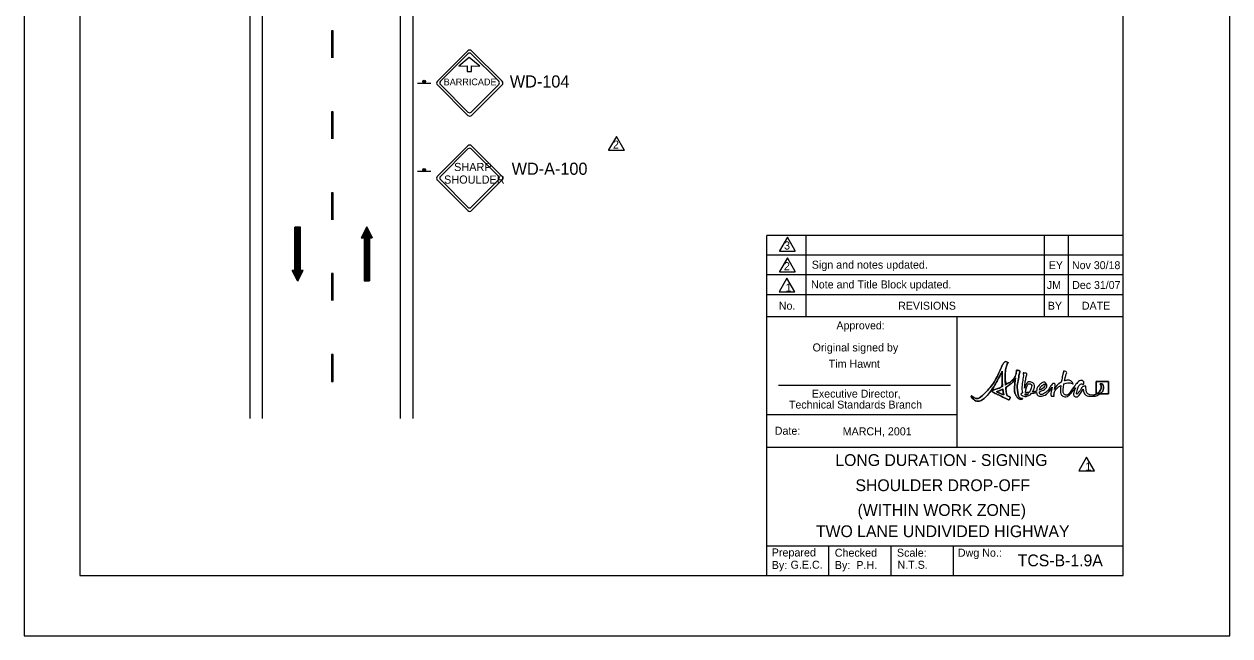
# Model space of a CAD drawing. Extents: x 1387 to 1603, y 134 to 413.
# Drawn here: x 1386.9 to 1602.9, y 133.8 to 243.5 of the extents above; entities that cross this region are included whole.
import ezdxf

# ---------------------------------------------------------------- set-up
doc = ezdxf.new("R2010")
doc.units = 0
for name, color, linetype in [('Level 10', 7, 'Continuous'), ('Level 2', 7, 'Continuous'), ('Level 44', 7, 'Continuous'), ('Level 53', 7, 'Continuous'), ('Level 60', 7, 'Continuous')]:
    doc.layers.add(name, color=color, linetype=linetype)

msp = doc.modelspace()

# ---------------------------------------------------------------- linework, layer by layer
at = {"layer": 'Level 10'}
for p, q in [((1427.31, 354.27), (1427.31, 172.77)), ((1429.55, 354.27), (1429.55, 172.77)), ((1454.23, 354.27), (1454.23, 172.77)), ((1456.49, 269.76), (1456.49, 172.77)), ((1435.4, 199.31), (1435.4, 207.05)), ((1436.37, 207.05), (1435.4, 207.05)), ((1435.4, 198.34), (1435.4, 207.05)), ((1435.52, 198.1), (1435.52, 207.05)), ((1435.64, 197.86), (1435.64, 207.05)), ((1435.76, 197.62), (1435.76, 207.05)), ((1435.88, 197.38), (1435.88, 207.05)), ((1436, 197.62), (1436, 207.05)), ((1436.12, 197.86), (1436.12, 207.05)), ((1436.25, 198.1), (1436.25, 207.05)), ((1436.37, 199.31), (1436.37, 207.05)), ((1436.37, 198.34), (1436.37, 207.05)), ((1448.25, 207.11), (1447.28, 205.17)), ((1447.4, 205.41), (1447.4, 205.17)), ((1447.53, 205.66), (1447.53, 205.17)), ((1447.65, 205.9), (1447.65, 205.17)), ((1447.77, 206.14), (1447.77, 197.43)), ((1447.89, 206.38), (1447.89, 197.43)), ((1448.01, 206.62), (1448.01, 197.43)), ((1448.13, 206.87), (1448.13, 197.43)), ((1448.25, 207.11), (1448.25, 197.43)), ((1448.25, 207.11), (1449.22, 205.17)), ((1448.37, 206.87), (1448.37, 197.43)), ((1448.49, 206.62), (1448.49, 197.43)), ((1448.61, 206.38), (1448.61, 197.43)), ((1448.73, 206.14), (1448.73, 197.43)), ((1448.86, 205.9), (1448.86, 205.17)), ((1448.98, 205.66), (1448.98, 205.17)), ((1449.1, 205.41), (1449.1, 205.17)), ((1447.28, 205.17), (1447.77, 205.17)), ((1447.77, 205.17), (1447.77, 197.43)), ((1448.73, 205.17), (1448.73, 197.43)), ((1448.73, 205.17), (1449.22, 205.17)), ((1435.88, 197.38), (1434.92, 199.31)), ((1435.4, 199.31), (1434.92, 199.31)), ((1435.04, 199.07), (1435.04, 199.31)), ((1435.16, 198.83), (1435.16, 199.31)), ((1435.28, 198.58), (1435.28, 199.31)), ((1435.88, 197.38), (1436.85, 199.31)), ((1436.85, 199.31), (1436.37, 199.31)), ((1436.49, 198.58), (1436.49, 199.31)), ((1436.61, 198.83), (1436.61, 199.31)), ((1436.73, 199.07), (1436.73, 199.31)), ((1447.77, 197.43), (1448.73, 197.43))]:
    msp.add_line(p, q, dxfattribs=at)
at = {"layer": 'Level 2'}
for p, q in [((1441.94, 242.26), (1441.94, 237.42)), ((1442.24, 242.26), (1441.94, 242.26)), ((1442.24, 237.42), (1442.24, 242.26)), ((1441.94, 227.74), (1441.94, 222.91)), ((1442.24, 227.74), (1441.94, 227.74)), ((1442.24, 222.91), (1442.24, 227.74)), ((1441.94, 213.23), (1441.94, 208.39)), ((1442.24, 213.23), (1441.94, 213.23)), ((1442.24, 208.39), (1442.24, 213.23)), ((1441.94, 198.72), (1441.94, 193.88)), ((1442.24, 198.72), (1441.94, 198.72)), ((1442.24, 193.88), (1442.24, 198.72)), ((1441.94, 184.2), (1441.94, 179.36)), ((1442.24, 184.2), (1441.94, 184.2)), ((1442.24, 179.36), (1442.24, 184.2)), ((1441.94, 179.36), (1442.24, 179.36))]:
    msp.add_line(p, q, dxfattribs=at)
at = {"layer": 'Level 44'}
for p, q in [((1466.38, 238.69), (1460.91, 233.22)), ((1461.45, 233.22), (1466.38, 238.14)), ((1466.97, 238.14), (1471.89, 233.22)), ((1472.5, 233.22), (1467.03, 238.69)), ((1466.62, 237.49), (1464.74, 235.91)), ((1464.74, 235.91), (1466.25, 235.99)), ((1466.25, 235.99), (1466.25, 234.99)), ((1468.51, 235.91), (1466.62, 237.49)), ((1467, 234.99), (1467, 235.99)), ((1467, 235.99), (1468.51, 235.91)), ((1466.25, 234.99), (1467, 234.99)), ((1457.34, 232.89), (1459.76, 232.89)), ((1460.91, 232.57), (1466.38, 227.1)), ((1460.91, 232.57), (1460.91, 232.57)), ((1466.38, 227.71), (1461.45, 232.63)), ((1471.89, 232.63), (1466.97, 227.71)), ((1467.03, 227.1), (1472.5, 232.57)), ((1466.39, 221.65), (1460.89, 216.17)), ((1461.44, 216.16), (1466.39, 221.1)), ((1466.97, 221.1), (1471.91, 216.16)), ((1472.52, 216.17), (1467.03, 221.65)), ((1457.34, 217.09), (1459.76, 217.09)), ((1460.89, 215.52), (1466.39, 210.03)), ((1460.9, 215.52), (1460.89, 215.52)), ((1466.39, 210.64), (1461.44, 215.58)), ((1471.91, 215.58), (1466.97, 210.64)), ((1467.03, 210.03), (1472.52, 215.52))]:
    msp.add_line(p, q, dxfattribs=at)
for centre, radius in [((1458.55, 233.16), 0.242), ((1458.55, 233.16), 0.121), ((1458.55, 217.36), 0.242), ((1458.55, 217.36), 0.121)]:
    msp.add_circle(centre, radius, dxfattribs=at)
for centre, radius, start, end in [((1466.71, 238.37), 0.458, 45, 135), ((1466.67, 237.85), 0.412, 45, 135), ((1461.23, 232.9), 0.458, 135, 225), ((1461.75, 232.92), 0.412, 135, 225), ((1471.6, 232.92), 0.412, 315, 45), ((1472.18, 232.9), 0.458, 315, 45), ((1466.67, 228), 0.412, 225, 315), ((1466.71, 227.42), 0.458, 225, 315), ((1466.71, 221.33), 0.459, 45, 135), ((1466.68, 220.81), 0.413, 45, 135), ((1461.22, 215.84), 0.459, 135, 225), ((1461.74, 215.87), 0.413, 135, 225), ((1471.62, 215.87), 0.413, 315, 45), ((1472.2, 215.84), 0.459, 315, 45), ((1466.68, 210.93), 0.413, 225, 315), ((1466.71, 210.35), 0.459, 225, 315)]:
    msp.add_arc(centre, radius, start, end, dxfattribs=at)
at = {"layer": 'Level 53'}
msp.add_line((1579.55, 177.14), (1579, 177.14), dxfattribs=at)
msp.add_lwpolyline([(1579.55, 177.14), (1581.16, 177.14), (1581.16, 179.37), (1578.93, 179.37), (1578.93, 177.14), (1579, 177.14)], dxfattribs=at)
for points, degree in [([(1565.56, 176.33), (1565.32, 176.37), (1565.01, 176.69), (1564.91, 177.23), (1564.74, 178.2), (1564.84, 179.15), (1565.13, 180.57), (1565.18, 180.84), (1565.36, 181.31), (1564.78, 181.4), (1564.59, 181.42), (1564.69, 181.33), (1564.64, 181.09), (1564.41, 180.03), (1563.55, 179.27), (1562.68, 178.75), (1562.59, 179.97), (1562.63, 181.31), (1562.85, 182.14), (1563.05, 182.83), (1563.28, 182.7), (1562.99, 182.85), (1562.69, 183.01), (1562.37, 182.8), (1562.11, 182.28), (1561.85, 181.77), (1560.66, 178.95), (1558.74, 177.05), (1557.77, 176.08), (1556.88, 176.58), (1556.7, 176.73), (1556.56, 176.85), (1556.51, 176.66), (1556.68, 176.47), (1557.48, 175.61), (1558.63, 176.1), (1559.05, 176.52), (1560.22, 177.69), (1561.57, 180.19), (1562.11, 181.25), (1562.06, 180.65), (1562.05, 179.65), (1562.16, 178.48), (1561.57, 178.19), (1561.04, 178.02), (1560.79, 177.95), (1560.51, 177.88), (1560.35, 177.77), (1560.34, 177.64), (1560.34, 177.51), (1560.52, 177.39), (1560.78, 177.27), (1561.25, 177.04), (1562.62, 176.4), (1562.96, 176.2), (1563.25, 176.03), (1563.39, 176.16), (1563.48, 176.34), (1563.59, 176.58), (1563.28, 176.72), (1562.98, 176.81), (1562.87, 177.2), (1562.78, 177.74), (1562.72, 178.33), (1563.41, 178.76), (1564.1, 179.33), (1564.5, 180.04), (1564.4, 179.45), (1564.14, 177.42), (1564.78, 176.56), (1564.92, 176.37), (1565.24, 176.16), (1565.54, 176.19), (1565.68, 176.21), (1565.76, 176.3), (1565.74, 176.33), (1565.73, 176.36), (1565.64, 176.32), (1565.56, 176.33)], 3), ([(1562.68, 178.75), (1562.59, 179.97), (1562.63, 181.31), (1562.85, 182.14), (1563.05, 182.83), (1563.28, 182.7), (1562.99, 182.85), (1562.69, 183.01), (1562.37, 182.8), (1562.11, 182.28), (1561.85, 181.77), (1560.66, 178.95), (1558.74, 177.05), (1557.77, 176.08), (1556.88, 176.58), (1556.7, 176.73), (1556.56, 176.85), (1556.51, 176.66), (1556.68, 176.47), (1557.48, 175.61), (1558.63, 176.1), (1559.05, 176.52), (1560.22, 177.69), (1561.57, 180.19), (1562.11, 181.25)], 3), ([(1562.11, 181.25), (1562.06, 180.65), (1562.05, 179.65), (1562.16, 178.48)], 2), ([(1565.56, 176.33), (1565.32, 176.37), (1565.01, 176.69), (1564.91, 177.23), (1564.74, 178.2), (1564.84, 179.15), (1565.13, 180.57), (1565.18, 180.84), (1565.36, 181.31), (1564.78, 181.4), (1564.59, 181.42), (1564.69, 181.33), (1564.64, 181.09), (1564.41, 180.03), (1563.55, 179.27), (1562.68, 178.75)], 3), ([(1562.72, 178.33), (1563.41, 178.76), (1564.1, 179.33), (1564.5, 180.04)], 2), ([(1564.5, 180.04), (1564.4, 179.45), (1564.14, 177.42), (1564.78, 176.56), (1564.92, 176.37), (1565.24, 176.16), (1565.54, 176.19), (1565.68, 176.21), (1565.76, 176.3), (1565.74, 176.33), (1565.73, 176.36), (1565.64, 176.32), (1565.56, 176.33)], 3), ([(1566.1, 178.17), (1566.14, 178.74), (1566.23, 179.43), (1566.36, 180.08), (1566.42, 180.35), (1566.6, 180.81), (1566.02, 180.9), (1565.83, 180.93), (1565.86, 180.84), (1565.88, 180.59), (1565.9, 180.26), (1565.52, 178.22), (1565.72, 177.32)], 3), ([(1567.54, 177.51), (1567.95, 178.18), (1567.91, 179.09), (1567.31, 179.25), (1566.6, 179.42), (1566.25, 178.74), (1566.1, 178.17)], 3), ([(1573.25, 179.51), (1573.32, 179.81), (1573.39, 180.11), (1573.47, 180.41), (1573.55, 180.68), (1573.77, 181.14), (1573.19, 181.23), (1573.01, 181.26), (1573.09, 181.17), (1573.03, 180.92), (1572.92, 180.47), (1572.78, 179.87), (1572.67, 179.28)], 3), ([(1578.31, 176.94), (1577.39, 176.94), (1577.15, 177.65), (1577.11, 178.01), (1577.08, 178.24), (1577.13, 178.58), (1576.73, 178.53), (1576.44, 178.5), (1576.19, 177.95), (1575.83, 177.49), (1575.52, 177.09), (1575.38, 177.13), (1575.46, 177.47), (1575.54, 177.9), (1575.9, 178.9), (1576.31, 178.98), (1576.5, 179.01), (1576.57, 178.68), (1576.66, 178.88), (1576.74, 179.09), (1576.66, 179.54), (1576.24, 179.54), (1575.94, 179.54), (1575.59, 179.23), (1575.29, 178.87), (1575.04, 178.56), (1573.76, 176.67), (1573.22, 177.08), (1572.96, 177.27), (1572.99, 178.04), (1573.14, 178.96)], 3), ([(1573.14, 178.96), (1573.78, 179.21), (1574.32, 179.13), (1574.62, 178.98), (1574.76, 178.91), (1574.79, 178.92), (1574.72, 179.08), (1574.63, 179.32), (1574.11, 179.7), (1573.31, 179.53), (1573.29, 179.52), (1573.27, 179.52), (1573.25, 179.51)], 3), ([(1578.93, 179.37), (1578.93, 179.37), (1578.93, 177.14), (1578.93, 177.14), (1578.93, 177.14), (1579, 177.14), (1579, 177.14), (1579.48, 177.43), (1579.81, 177.98), (1579.8, 178.44), (1579.8, 178.83), (1579.6, 178.81), (1579.62, 178.87), (1579.69, 179.03), (1580.18, 178.94), (1580.21, 178.38), (1580.23, 177.91), (1579.99, 177.45), (1579.55, 177.14), (1579.55, 177.14), (1581.16, 177.14), (1581.16, 177.14), (1581.16, 177.14), (1581.16, 179.37), (1581.16, 179.37), (1581.16, 179.37), (1578.93, 179.37), (1578.93, 179.37)], 3), ([(1562.16, 178.48), (1561.57, 178.19), (1561.04, 178.02), (1560.79, 177.95), (1560.51, 177.88), (1560.35, 177.77), (1560.34, 177.64), (1560.34, 177.51), (1560.52, 177.39), (1560.78, 177.27), (1561.25, 177.04), (1562.62, 176.4), (1562.96, 176.2), (1563.25, 176.03), (1563.39, 176.16), (1563.48, 176.34), (1563.59, 176.58), (1563.28, 176.72), (1562.98, 176.81)], 3), ([(1561.09, 177.54), (1561.4, 177.66), (1561.79, 177.82), (1562.2, 178.04)], 2), ([(1561.09, 177.54), (1561.4, 177.66), (1561.79, 177.82), (1562.2, 178.04), (1562.26, 177.56), (1562.32, 177.22), (1562.39, 176.97), (1562.09, 177.08), (1561.65, 177.25), (1561.09, 177.54)], 3), ([(1562.39, 176.97), (1562.09, 177.08), (1561.65, 177.25), (1561.09, 177.54)], 2), ([(1562.2, 178.04), (1562.26, 177.56), (1562.32, 177.22), (1562.39, 176.97)], 2), ([(1562.98, 176.81), (1562.87, 177.2), (1562.78, 177.74), (1562.72, 178.33)], 2), ([(1565.72, 177.32), (1565.47, 177.24), (1565.36, 177.05), (1565.69, 176.85), (1565.91, 176.71), (1566.4, 176.67), (1566.9, 176.91), (1567.07, 177), (1567.23, 177.12), (1567.35, 177.27)], 3), ([(1566.17, 176.95), (1566.2, 176.98), (1566.22, 177.02), (1566.22, 177.07), (1566.22, 177.1), (1566.23, 177.13), (1566.23, 177.16)], 3), ([(1566.23, 177.16), (1566.35, 177.17), (1566.55, 177.18), (1566.78, 177.2)], 2), ([(1566.25, 177.38), (1566.34, 178.1), (1566.71, 179.09), (1567.18, 178.93), (1567.45, 178.84), (1567.31, 178), (1566.96, 177.44)], 3), ([(1566.96, 177.44), (1566.74, 177.42), (1566.5, 177.4), (1566.25, 177.38)], 2), ([(1566.78, 177.2), (1566.66, 177.07), (1566.52, 176.97), (1566.37, 176.95)], 2), ([(1567.35, 177.27), (1567.65, 177.3), (1567.96, 177.35), (1568.24, 177.41)], 2), ([(1568.24, 177.63), (1568.03, 177.59), (1567.8, 177.55), (1567.54, 177.51)], 2), ([(1568.76, 177.53), (1568.86, 177.56), (1568.94, 177.59), (1569.02, 177.63), (1569.9, 178.02), (1570.2, 178.61), (1569.98, 178.97), (1569.77, 179.31), (1569.16, 179.2), (1568.68, 178.7), (1568.44, 178.45), (1568.26, 178.02), (1568.24, 177.63)], 3), ([(1568.24, 177.41), (1568.29, 177.02), (1568.55, 176.71), (1569.14, 176.77), (1569.99, 176.85), (1570.74, 177.89), (1571.02, 178.39)], 3), ([(1571.44, 177.95), (1571.49, 178.22), (1571.58, 178.53), (1571.58, 178.74), (1571.59, 178.95), (1571.44, 179), (1571.38, 179.02), (1571.26, 179.06), (1571.11, 178.99), (1570.95, 178.78), (1570.6, 178.28), (1570.15, 177.5), (1569.47, 177.17), (1568.99, 176.93), (1568.77, 177.17), (1568.76, 177.53)], 3), ([(1569.23, 178.65), (1569.53, 178.93), (1569.68, 178.91), (1569.72, 178.83), (1569.8, 178.67), (1569.45, 178.11), (1568.78, 177.8)], 3), ([(1568.78, 177.8), (1568.84, 178.11), (1569, 178.44), (1569.23, 178.65)], 2), ([(1571.02, 178.39), (1570.97, 177.85), (1570.62, 176.68), (1571.22, 176.74), (1571.45, 176.76), (1571.35, 176.8), (1571.37, 177), (1571.42, 177.71), (1572, 178.31), (1572.59, 178.68)], 3), ([(1572.67, 179.28), (1572.2, 179), (1571.76, 178.55), (1571.44, 177.95)], 2), ([(1572.59, 178.68), (1572.49, 177.81), (1572.52, 177.04), (1572.91, 176.79), (1573.64, 176.34), (1574.66, 177.53), (1575.22, 178.26)], 3), ([(1575.22, 178.26), (1574.93, 177.61), (1574.77, 176.78), (1575.2, 176.66), (1575.71, 176.51), (1576.1, 177.35), (1576.57, 177.99)], 3), ([(1576.57, 177.99), (1576.62, 177.53), (1576.93, 176.74), (1578.17, 176.74), (1578.72, 176.74), (1579.2, 176.89), (1579.55, 177.14)], 3), ([(1579, 177.14), (1578.79, 177.02), (1578.56, 176.94), (1578.31, 176.94)], 2), ([(1579, 177.14), (1579.48, 177.43), (1579.81, 177.98), (1579.8, 178.44), (1579.8, 178.83), (1579.6, 178.81), (1579.62, 178.87), (1579.69, 179.03), (1580.18, 178.94), (1580.21, 178.38), (1580.23, 177.91), (1579.99, 177.45), (1579.55, 177.14)], 3), ([(1566.37, 176.95), (1566.29, 176.94), (1566.23, 176.94), (1566.17, 176.95)], 2)]:
    msp.add_open_spline(points, degree=degree, dxfattribs=at)
at = {"layer": 'Level 60'}
for p, q in [((1583.78, 205.58), (1519.9, 205.58)), ((1519.91, 199.11), (1519.91, 205.58)), ((1527, 199.11), (1527, 205.58)), ((1569.59, 205.58), (1569.59, 191.03)), ((1573.9, 205.58), (1573.9, 191.03)), ((1583.78, 202.03), (1519.9, 202.03)), ((1519.91, 191.03), (1519.91, 199.11)), ((1527, 191.03), (1527, 199.11)), ((1583.78, 198.48), (1519.9, 198.48)), ((1583.78, 194.93), (1519.9, 194.93)), ((1519.91, 144.56), (1519.91, 191.03)), ((1519.91, 191.03), (1583.78, 191.03)), ((1553.96, 191.03), (1553.96, 167.62)), ((1553.96, 191.03), (1553.96, 191.03)), ((1553.97, 191.03), (1553.97, 191.03)), ((1522.02, 178.71), (1552.82, 178.71)), ((1519.91, 173.47), (1553.96, 173.47)), ((1519.91, 167.62), (1583.75, 167.62)), ((1519.91, 149.88), (1583.75, 149.88)), ((1531.04, 144.56), (1531.04, 149.88)), ((1542.17, 144.56), (1542.17, 149.88)), ((1553.3, 149.88), (1553.3, 144.56)), ((1396.88, 144.56), (1396.88, 144.56)), ((1386.88, 133.75), (1386.88, 133.75))]:
    msp.add_line(p, q, dxfattribs=at)
for points in [[(1602.88, 412.75), (1386.88, 412.75), (1386.88, 133.75), (1602.88, 133.75)], [(1583.75, 401.95), (1396.88, 401.95), (1396.88, 144.56), (1583.75, 144.56)], [(1523.53, 197.91), (1522.11, 195.44), (1524.95, 195.44)], [(1577.22, 165.82), (1575.8, 163.35), (1578.64, 163.35)]]:
    msp.add_lwpolyline(points, close=True, dxfattribs=at)
for points in [[(1492.98, 223.33), (1491.59, 220.91)], [(1494.38, 220.91), (1492.98, 223.33)], [(1491.59, 220.91), (1491.56, 220.86), (1494.4, 220.86), (1494.38, 220.91)], [(1523.61, 205.25), (1522.21, 202.82)], [(1525, 202.82), (1523.61, 205.25)], [(1522.21, 202.82), (1522.19, 202.78), (1525.03, 202.78), (1525, 202.82)], [(1523.61, 201.53), (1522.21, 199.11)], [(1525, 199.11), (1523.61, 201.53)], [(1522.21, 199.11), (1522.19, 199.06), (1525.03, 199.06), (1525, 199.11)]]:
    msp.add_lwpolyline(points, dxfattribs=at)

# ---------------------------------------------------------------- texts
at = {"layer": 'Level 10'}
for s, p in [('WD-104', (1473.88, 232.1)), ('WD-A-100', (1474.21, 216.45))]:
    msp.add_text(s, height=2.177, rotation=360, dxfattribs=at).set_placement(p)
at = {"layer": 'Level 44'}
for s, height, p in [('BARRICADE', 1.214, (1462.03, 232.5)), ('SHARP', 1.461, (1463.9, 217.12)), ('SHOULDER', 1.461, (1462.1, 214.86))]:
    msp.add_text(s, height=height, rotation=360, dxfattribs=at).set_placement(p)
at = {"layer": 'Level 60'}
for s, height, p in [('2', 1.45, (1492.35, 221.13)), ('3', 1.45, (1523, 203.05)), ('EY', 1.419, (1570.44, 199.53)), ('Nov 30/18', 1.419, (1574.6, 199.53)), ('2', 1.45, (1522.98, 199.33)), ('1', 1.45, (1523.3, 195.5)), ('JM', 1.419, (1570.09, 195.98)), ('Dec 31/07', 1.419, (1574.63, 195.98)), ('No.', 1.419, (1522.08, 192.26)), ('REVISIONS', 1.419, (1543.46, 192.26)), ('BY', 1.419, (1570.27, 192.26)), ('DATE', 1.419, (1576.37, 192.26)), ('Date:', 1.433, (1521.34, 169.83)), ('LONG DURATION - SIGNING', 2.115, (1532.19, 164.23)), ('1', 1.45, (1576.99, 163.41)), ('Prepared', 1.44, (1520.8, 148)), ('Checked', 1.433, (1532.1, 147.96)), ('Scale:', 1.433, (1543.23, 147.96)), ('Dwg No.:', 1.433, (1554.15, 147.96)), ('By:', 1.44, (1520.8, 145.75)), ('G.E.C. ', 1.433, (1524.18, 145.81)), ('By:  P.H.', 1.44, (1532.1, 145.75)), ('    N.T.S.   ', 1.4329, (1541.2, 145.79))]:
    msp.add_text(s, height=height, rotation=360, dxfattribs=at).set_placement(p)
for s, height, p in [('Sign and notes updated.', 1.434, (1527.98, 199.61)), ('Note and Title Block updated.', 1.434, (1527.84, 196.07)), ('Approved:', 1.419, (1532.4, 188.73)), ('Original signed by', 1.434, (1528.12, 184.77)), ('Tim Hawnt', 1.434, (1531.01, 181.84)), ('Executive Director,', 1.4187, (1527.99, 176.49)), ('Technical Standards Branch', 1.4187, (1523.89, 174.53)), ('MARCH, 2001', 1.434, (1533.51, 169.72)), ('SHOULDER DROP-OFF', 2.1152, (1535.8, 159.72)), ('(WITHIN WORK ZONE)', 2.115, (1536.19, 155.27)), ('TWO LANE UNDIVIDED HIGHWAY', 2.1152, (1528.73, 151.47)), ('TCS-B-1.9A', 2.115, (1564.87, 146.24))]:
    msp.add_text(s, height=height, dxfattribs=at).set_placement(p)

doc.saveas('drawing.dxf')
